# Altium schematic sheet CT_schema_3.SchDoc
size 294 x 169 mm
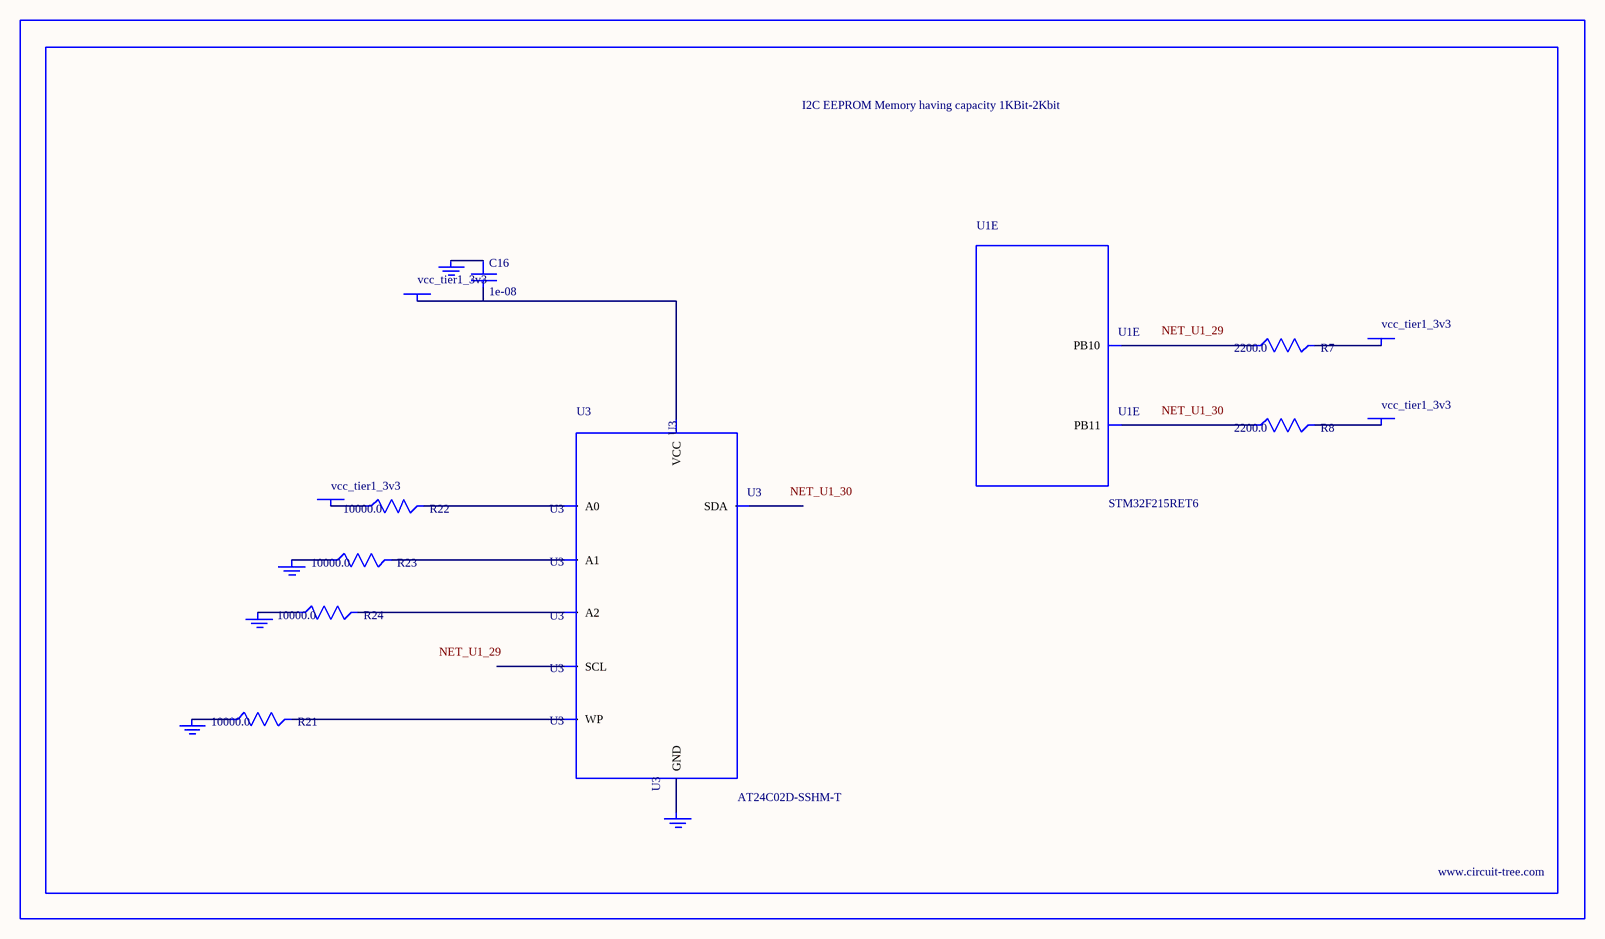
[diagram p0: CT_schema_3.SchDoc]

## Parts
BORDER2  (no value)
C16  1e-08  [C0402]
GND_INSTANCE_2_0  (no value)
GND_INSTANCE_2_1  (no value)
GND_INSTANCE_2_2  (no value)
GND_INSTANCE_2_3  (no value)
GND_INSTANCE_2_4  (no value)
POWER_INSTANCE_2_0  vcc_tier1_3v3
POWER_INSTANCE_2_1  vcc_tier1_3v3
POWER_INSTANCE_2_2  vcc_tier1_3v3
POWER_INSTANCE_2_3  vcc_tier1_3v3
R7  2200.0  [R0603]
R8  2200.0  [R0603]
R21  10000.0  [R0603]
R22  10000.0  [R0603]
R23  10000.0  [R0603]
R24  10000.0  [R0603]
U1  STM32F215RET6  [LQFP64]  (part E of 7)
U3  AT24C02D-SSHM-T  [AT24C02D]

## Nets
NetC16_1: C16.1 GND_INSTANCE_2_3.0(GND)
NetC16_2: C16.2 POWER_INSTANCE_2_1.0(PWR) U3.8(VCC)
NetGND_INSTANCE_2_0_0: GND_INSTANCE_2_0.0(GND) R23.1
NetGND_INSTANCE_2_1_0: GND_INSTANCE_2_1.0(GND) R24.1
NetGND_INSTANCE_2_2_0: GND_INSTANCE_2_2.0(GND) R21.1
NetGND_INSTANCE_2_4_0: GND_INSTANCE_2_4.0(GND) U3.4(GND)
NetPOWER_INSTANCE_2_0_0: POWER_INSTANCE_2_0.0(PWR) R22.1
NetPOWER_INSTANCE_2_2_0: POWER_INSTANCE_2_2.0(PWR) R7.2
NetPOWER_INSTANCE_2_3_0: POWER_INSTANCE_2_3.0(PWR) R8.2
NetR7_1: R7.1 U1.29(PB10)
NetR8_1: R8.1 U1.30(PB11)
NetR21_2: R21.2 U3.7(WP)
NetR22_2: R22.2 U3.1(A0)
NetR23_2: R23.2 U3.2(A1)
NetR24_2: R24.2 U3.3(A2)

Not connected (* = marked no-connect by the designer): U3 5(SDA) 6(SCL)

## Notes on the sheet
- Labels drawn without touching a wire or pin: NET_U1_29, NET_U1_30

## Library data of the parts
BORDER2 = BORDER_PAGE2
C16 = C0402C103K3RAC
GND_INSTANCE_2_0-GND_INSTANCE_2_4 = GND
POWER_INSTANCE_2_0-POWER_INSTANCE_2_3 = PWR
R7 R8 = RC0603JR-072K2L
R21-R24 = RC0603JR-0710KL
